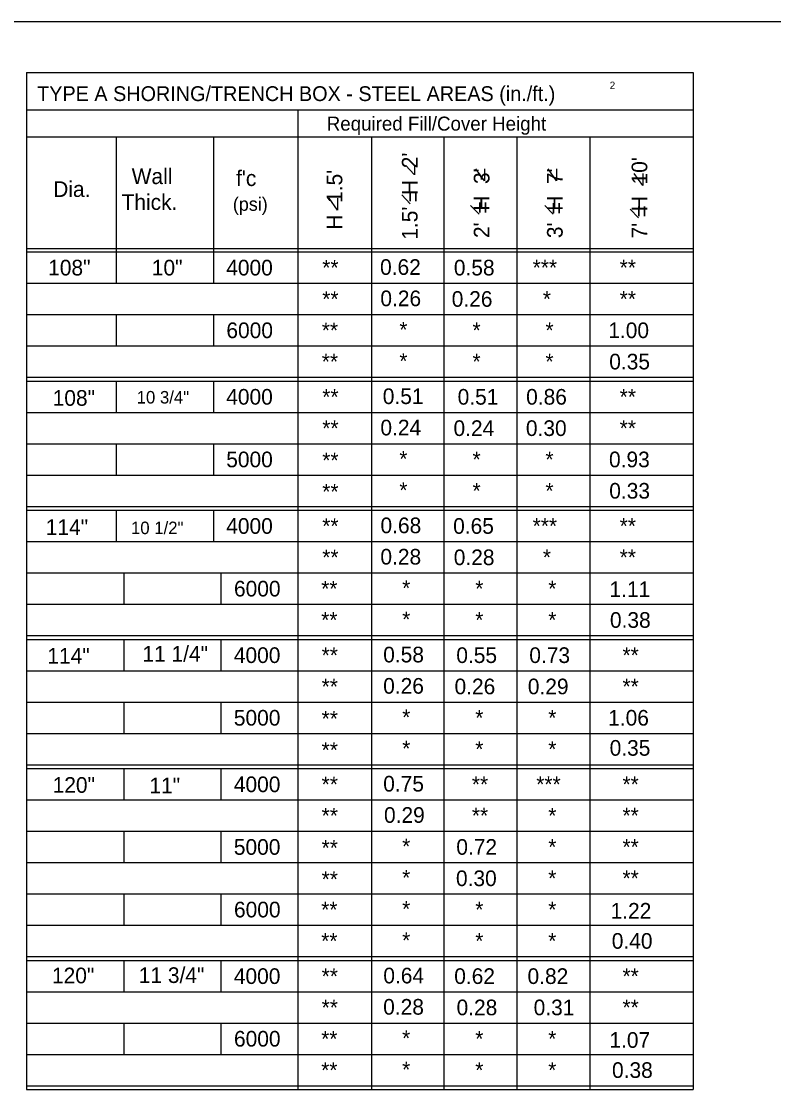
# Model space of a CAD drawing. Extents: x -22562 to -18409, y 3991 to 7171.
# Drawn here: x -19874.5 to -19722.1, y 4353.9 to 4570.4 of the extents above; entities that cross this region are included whole.
import ezdxf

# ---------------------------------------------------------------- set-up
doc = ezdxf.new("R2010")
doc.units = 0
for name, color, linetype in [('1', 7, 'Continuous'), ('2', 7, 'Continuous'), ('3', 7, 'Continuous'), ('4', 7, 'Continuous')]:
    doc.layers.add(name, color=color, linetype=linetype)

msp = doc.modelspace()

# ---------------------------------------------------------------- linework, layer by layer
at = {"layer": '1'}
for p, q in [((-19794.92, 4539.37), (-19796.64, 4541.13)), ((-19794.83, 4539.28), (-19794.83, 4541.03)), ((-19795.73, 4533.42), (-19797.45, 4535.19)), ((-19781.81, 4531.28), (-19783.53, 4533.04)), ((-19766.76, 4531.3), (-19768.48, 4533.07)), ((-19749.48, 4530.55), (-19751.2, 4532.32))]:
    msp.add_line(p, q, dxfattribs=at)
at = {"layer": '2'}
for p, q in [((-20344.85, 4570.37), (-19558.85, 4570.37)), ((-19873.51, 4560.02), (-19738.44, 4560.02)), ((-19873.51, 4560.02), (-19873.51, 4353.9)), ((-19738.44, 4560.02), (-19738.44, 4353.9)), ((-19873.51, 4552.45), (-19738.44, 4552.45)), ((-19818.51, 4552.45), (-19818.51, 4353.9)), ((-19873.51, 4546.94), (-19738.44, 4546.94)), ((-19855.34, 4546.94), (-19855.34, 4517.29)), ((-19835.63, 4546.94), (-19835.63, 4517.29)), ((-19803.62, 4546.94), (-19803.62, 4353.9)), ((-19788.95, 4546.94), (-19788.95, 4353.9)), ((-19774.16, 4546.94), (-19774.16, 4353.9)), ((-19759.38, 4546.94), (-19759.38, 4353.9)), ((-19873.51, 4524.36), (-19738.44, 4524.36)), ((-19873.51, 4523.67), (-19738.44, 4523.67)), ((-19873.51, 4517.29), (-19738.44, 4517.29)), ((-19873.51, 4510.95), (-19738.44, 4510.95)), ((-19855.34, 4510.95), (-19855.34, 4504.6)), ((-19835.63, 4510.95), (-19835.63, 4504.6)), ((-19873.51, 4504.6), (-19738.44, 4504.6)), ((-19873.51, 4498.25), (-19738.44, 4498.25)), ((-19873.51, 4498.25), (-19738.44, 4498.25)), ((-19873.51, 4497.46), (-19738.44, 4497.46)), ((-19855.34, 4497.46), (-19855.34, 4491.12)), ((-19835.63, 4497.46), (-19835.63, 4491.12)), ((-19873.51, 4491.12), (-19738.44, 4491.12)), ((-19873.51, 4484.77), (-19738.44, 4484.77)), ((-19855.34, 4484.77), (-19855.34, 4478.42)), ((-19835.63, 4484.77), (-19835.63, 4478.42)), ((-19873.51, 4478.42), (-19738.44, 4478.42)), ((-19873.51, 4472.08), (-19738.44, 4472.08)), ((-19873.51, 4472.08), (-19738.44, 4472.08)), ((-19873.51, 4471.29), (-19738.44, 4471.29)), ((-19855.34, 4471.29), (-19855.34, 4464.94)), ((-19835.63, 4471.29), (-19835.63, 4464.94)), ((-19873.51, 4464.94), (-19738.44, 4464.94)), ((-19873.51, 4458.6), (-19738.44, 4458.6)), ((-19853.8, 4458.6), (-19853.8, 4452.25)), ((-19834.09, 4458.6), (-19834.09, 4452.25)), ((-19873.51, 4452.25), (-19738.44, 4452.25)), ((-19873.51, 4445.91), (-19738.44, 4445.91)), ((-19873.51, 4445.91), (-19738.44, 4445.91)), ((-19873.51, 4445.12), (-19738.44, 4445.12)), ((-19853.8, 4445.11), (-19853.8, 4438.77)), ((-19834.09, 4445.11), (-19834.09, 4438.77)), ((-19873.51, 4438.77), (-19738.44, 4438.77)), ((-19873.51, 4432.42), (-19738.44, 4432.42)), ((-19853.8, 4432.42), (-19853.8, 4426.07)), ((-19834.09, 4432.42), (-19834.09, 4426.07)), ((-19873.51, 4426.08), (-19738.44, 4426.08)), ((-19873.51, 4419.73), (-19738.44, 4419.73)), ((-19873.51, 4419.73), (-19738.44, 4419.73)), ((-19873.51, 4418.94), (-19738.44, 4418.94)), ((-19853.8, 4418.94), (-19853.8, 4412.59)), ((-19853.8, 4418.94), (-19853.8, 4412.59)), ((-19834.09, 4418.94), (-19834.09, 4412.59)), ((-19834.09, 4418.94), (-19834.09, 4412.59)), ((-19873.51, 4412.59), (-19738.44, 4412.59)), ((-19873.51, 4406.25), (-19738.44, 4406.25)), ((-19853.8, 4406.25), (-19853.8, 4399.9)), ((-19834.09, 4406.25), (-19834.09, 4399.9)), ((-19873.51, 4399.9), (-19738.44, 4399.9)), ((-19873.51, 4393.56), (-19738.44, 4393.56)), ((-19853.8, 4393.56), (-19853.8, 4387.21)), ((-19834.09, 4393.56), (-19834.09, 4387.21)), ((-19873.51, 4387.21), (-19738.44, 4387.21)), ((-19873.51, 4380.86), (-19738.44, 4380.86)), ((-19873.51, 4380.07), (-19738.44, 4380.07)), ((-19853.8, 4380.07), (-19853.8, 4373.73)), ((-19834.09, 4380.07), (-19834.09, 4373.73)), ((-19873.51, 4373.73), (-19738.44, 4373.73)), ((-19873.51, 4367.38), (-19738.44, 4367.38)), ((-19853.8, 4367.38), (-19853.8, 4361.03)), ((-19834.09, 4367.38), (-19834.09, 4361.03)), ((-19873.51, 4361.03), (-19738.44, 4361.03)), ((-19873.51, 4354.69), (-19738.44, 4354.69)), ((-19873.51, 4353.9), (-19738.44, 4353.9))]:
    msp.add_line(p, q, dxfattribs=at)
at = {"layer": '3'}
for points in [[(-19780.71, 4540.49), (-19780.71, 4538.08), (-19782.43, 4540.51)], [(-19766.08, 4540.49), (-19766.08, 4538.08), (-19767.8, 4540.51)], [(-19748.62, 4539.51), (-19748.62, 4537.1), (-19750.34, 4539.52)], [(-19810.46, 4534.53), (-19810.46, 4532.12), (-19812.18, 4534.55)]]:
    msp.add_lwpolyline(points, dxfattribs=at)

# ---------------------------------------------------------------- texts
at = {"layer": '1'}
for s, height, p in [("f'c", 3.172, (-19831.04, 4537)), ('Thick.', 3.172, (-19854.24, 4532.16)), ('(psi)', 2.719, (-19831.69, 4531.98)), ('**', 3.173, (-19753.31, 4518.88)), ('**', 3.173, (-19753.31, 4512.53)), ('10 3/4"', 2.538, (-19851.18, 4492.93)), ('**', 3.173, (-19753.31, 4492.7)), ('**', 3.173, (-19753.31, 4486.35)), ('10 1/2"', 2.538, (-19852.33, 4466.46)), ('**', 3.173, (-19753.31, 4466.53)), ('**', 3.173, (-19753.31, 4460.18)), ('1.11', 3.172, (-19755.38, 4453.71)), ('11 1/4"', 3.172, (-19850.01, 4440.63)), ('**', 3.173, (-19752.74, 4440.35)), ('**', 3.173, (-19752.74, 4434.01)), ('11"', 3.172, (-19848.59, 4413.95)), ('**', 3.173, (-19783.26, 4414.18)), ('**', 3.173, (-19752.74, 4414.18)), ('**', 3.173, (-19783.26, 4407.84)), ('**', 3.173, (-19752.74, 4407.84)), ('**', 3.173, (-19752.74, 4401.49)), ('**', 3.173, (-19752.74, 4395.14)), ('11 3/4"', 3.172, (-19850.75, 4375.51)), ('**', 3.173, (-19752.74, 4375.31)), ('**', 3.173, (-19752.74, 4368.97))]:
    msp.add_text(s, height=height, dxfattribs=at).set_placement(p)
for p in [(-19793.68, 4533.66), (-19779.54, 4531.4), (-19764.62, 4531.28), (-19747.36, 4530.63)]:
    msp.add_text('=', height=3.17, rotation=90, dxfattribs=at).set_placement(p)
at = {"layer": '2'}
for s, height, p in [('TYPE A SHORING/TRENCH BOX - STEEL AREAS (in./ft.)', 3, (-19871.34, 4554.22)), ('2', 1.5, (-19755.33, 4556.66)), ('Required Fill/Cover Height', 2.8357, (-19812.66, 4548.23)), ('Wall', 3.172, (-19852.18, 4537.39)), ('Dia.', 3.172, (-19868.09, 4534.79))]:
    msp.add_text(s, height=height, dxfattribs=at).set_placement(p)
at = {"layer": '3'}
for s, height, p in [('0.62', 3.172, (-19801.86, 4519)), ('0.58', 3.172, (-19786.91, 4518.88)), ('**', 3.173, (-19813.57, 4518.87)), ('***', 3.172, (-19770.94, 4518.88)), ('**', 3.173, (-19813.57, 4512.52)), ('0.26', 3.173, (-19801.8, 4512.65)), ('0.26', 3.172, (-19787.34, 4512.53)), ('*', 3.17, (-19768.88, 4512.53)), ('**', 3.173, (-19813.67, 4506.17)), ('*', 3.17, (-19797.95, 4506.31)), ('*', 3.17, (-19783.13, 4506.18)), ('*', 3.17, (-19768.35, 4506.18)), ('1.00', 3.173, (-19755.62, 4506.18)), ('**', 3.173, (-19813.67, 4499.83)), ('*', 3.17, (-19797.95, 4499.96)), ('*', 3.17, (-19783.13, 4499.84)), ('*', 3.17, (-19768.35, 4499.84)), ('0.35', 3.173, (-19755.42, 4499.84)), ('**', 3.173, (-19813.57, 4492.69)), ('0.51', 3.173, (-19801.31, 4492.82)), ('0.51', 3.172, (-19786.14, 4492.7)), ('0.86', 3.172, (-19772.26, 4492.7)), ('0.24', 3.173, (-19801.79, 4486.47)), ('**', 3.173, (-19813.57, 4486.34)), ('0.24', 3.172, (-19786.98, 4486.35)), ('0.30', 3.172, (-19772.31, 4486.35)), ('*', 3.17, (-19797.95, 4480.13)), ('*', 3.17, (-19783.13, 4480.01)), ('*', 3.17, (-19768.35, 4480.01)), ('0.93', 3.173, (-19755.47, 4480.01)), ('**', 3.173, (-19813.57, 4479.83)), ('**', 3.173, (-19813.57, 4473.48)), ('*', 3.17, (-19797.95, 4473.78)), ('*', 3.17, (-19783.13, 4473.66)), ('*', 3.17, (-19768.35, 4473.66)), ('0.33', 3.173, (-19755.42, 4473.66)), ('**', 3.173, (-19813.57, 4466.52)), ('0.68', 3.172, (-19801.77, 4466.65)), ('0.65', 3.172, (-19787.05, 4466.53)), ('***', 3.172, (-19770.94, 4466.53)), ('**', 3.173, (-19813.57, 4460.17)), ('0.28', 3.173, (-19801.79, 4460.3)), ('0.28', 3.172, (-19786.93, 4460.18)), ('*', 3.17, (-19768.88, 4460.19)), ('*', 3.17, (-19797.38, 4453.95)), ('**', 3.173, (-19813.79, 4453.82)), ('*', 3.17, (-19782.57, 4453.83)), ('*', 3.17, (-19767.78, 4453.83)), ('**', 3.173, (-19813.79, 4447.48)), ('*', 3.17, (-19797.38, 4447.61)), ('*', 3.17, (-19782.57, 4447.49)), ('*', 3.17, (-19767.78, 4447.49)), ('0.38', 3.173, (-19755.28, 4447.48)), ('**', 3.173, (-19813.7, 4440.34)), ('0.58', 3.172, (-19801.22, 4440.47)), ('0.55', 3.172, (-19786.41, 4440.35)), ('0.73', 3.172, (-19771.62, 4440.35)), ('**', 3.173, (-19813.7, 4433.99)), ('0.26', 3.173, (-19801.23, 4434.13)), ('0.26', 3.172, (-19786.77, 4434.01)), ('0.29', 3.172, (-19771.92, 4434.01)), ('**', 3.173, (-19813.7, 4427.48)), ('*', 3.17, (-19797.38, 4427.78)), ('*', 3.17, (-19782.57, 4427.66)), ('*', 3.17, (-19767.78, 4427.66)), ('1.06', 3.173, (-19755.64, 4427.66)), ('0.35', 3.173, (-19755.34, 4421.56)), ('**', 3.173, (-19813.7, 4421.13)), ('*', 3.17, (-19797.38, 4421.44)), ('*', 3.17, (-19782.57, 4421.32)), ('*', 3.17, (-19767.78, 4421.32)), ('**', 3.173, (-19813.7, 4414.17)), ('0.75', 3.172, (-19801.22, 4414.3)), ('***', 3.172, (-19770.21, 4414.18)), ('**', 3.173, (-19813.7, 4407.82)), ('0.29', 3.172, (-19801.06, 4407.96)), ('*', 3.17, (-19767.78, 4407.83)), ('**', 3.173, (-19813.7, 4401.31)), ('*', 3.17, (-19797.39, 4401.61)), ('0.72', 3.172, (-19786.41, 4401.49)), ('*', 3.17, (-19767.78, 4401.49)), ('**', 3.173, (-19813.7, 4394.96)), ('*', 3.17, (-19797.39, 4395.26)), ('0.30', 3.172, (-19786.48, 4395.14)), ('*', 3.17, (-19767.79, 4395.14)), ('**', 3.173, (-19813.79, 4388.78)), ('*', 3.17, (-19797.39, 4388.92)), ('*', 3.17, (-19782.57, 4388.8)), ('*', 3.17, (-19767.79, 4388.8)), ('1.22', 3.173, (-19755.15, 4388.55)), ('*', 3.17, (-19797.39, 4382.57)), ('**', 3.173, (-19813.79, 4382.44)), ('*', 3.17, (-19782.57, 4382.45)), ('*', 3.17, (-19767.79, 4382.45)), ('0.40', 3.173, (-19754.91, 4382.45)), ('**', 3.173, (-19813.7, 4375.3)), ('0.64', 3.172, (-19801.2, 4375.43)), ('0.62', 3.172, (-19786.83, 4375.31)), ('0.82', 3.172, (-19771.98, 4375.31)), ('**', 3.173, (-19813.7, 4368.95)), ('0.28', 3.173, (-19801.23, 4369.09)), ('0.28', 3.172, (-19786.36, 4368.97)), ('0.31', 3.172, (-19770.74, 4368.97)), ('**', 3.173, (-19813.79, 4362.6)), ('*', 3.17, (-19797.39, 4362.74)), ('*', 3.17, (-19782.57, 4362.62)), ('*', 3.17, (-19767.79, 4362.62)), ('1.07', 3.173, (-19755.39, 4362.37)), ('**', 3.173, (-19813.79, 4356.26)), ('*', 3.17, (-19797.39, 4356.39)), ('*', 3.17, (-19782.57, 4356.27)), ('*', 3.17, (-19767.79, 4356.27)), ('0.38', 3.173, (-19754.86, 4356.27))]:
    msp.add_text(s, height=height, dxfattribs=at).set_placement(p)
at = {"layer": '4'}
for s, height, p in [("1.5'  H  2'", 3.1718, (-19794.26, 4526.12)), ("7'  H  10'", 3.172, (-19747.71, 4526.37)), ("H  1.5'", 3.172, (-19809.51, 4528.16)), ("2'  H  3'", 3.172, (-19779.69, 4526.46)), ("3'  H  7'", 3.172, (-19764.86, 4526.44))]:
    msp.add_text(s, height=height, rotation=90, dxfattribs=at).set_placement(p)
for s, p in [('108"', (-19869.11, 4518.88)), ('10"', (-19848.11, 4518.88)), ('4000', (-19833.03, 4518.88)), ('6000', (-19833, 4506.18)), ('108"', (-19868.2, 4492.47)), ('4000', (-19833.03, 4492.7)), ('5000', (-19833.03, 4480.01)), ('114"', (-19869.59, 4466.3)), ('4000', (-19833.03, 4466.53)), ('6000', (-19831.46, 4453.83)), ('114"', (-19869.27, 4440.23)), ('4000', (-19831.49, 4440.35)), ('5000', (-19831.49, 4427.66)), ('120"', (-19868.21, 4414.05)), ('4000', (-19831.49, 4414.18)), ('5000', (-19831.49, 4401.49)), ('6000', (-19831.46, 4388.8)), ('120"', (-19868.34, 4375.44)), ('4000', (-19831.49, 4375.31)), ('6000', (-19831.46, 4362.62))]:
    msp.add_text(s, height=3.173, dxfattribs=at).set_placement(p)

doc.saveas('drawing.dxf')
